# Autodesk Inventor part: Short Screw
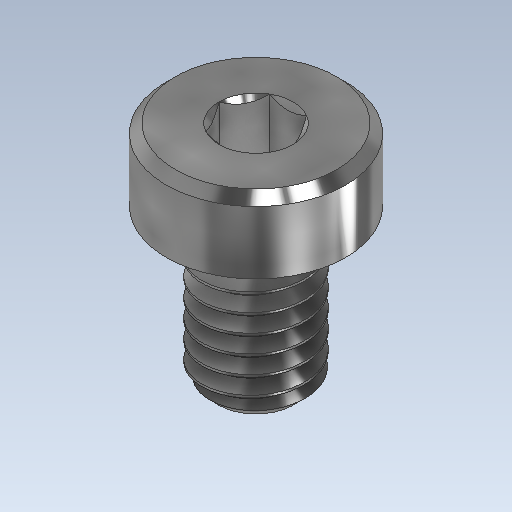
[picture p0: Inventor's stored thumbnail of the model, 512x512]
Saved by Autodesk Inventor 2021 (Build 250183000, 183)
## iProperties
Created: 2013-10
Part Number: Short Screw
Material: Generic
Description: STEP AP203
Document SubType Name: Modeling
Designer: bestm
Density: 1 g/cm^3
Appearance: Steel Galvanized
Sending System: SolidWorks 2010
Preprocessor: SwSTEP 2.0
Title: 93070A095.step
Revision Number: ANY
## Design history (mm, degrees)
feature "Cut-Extrude2"
body "Solid1"
